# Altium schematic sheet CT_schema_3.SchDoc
size 322 x 229 mm
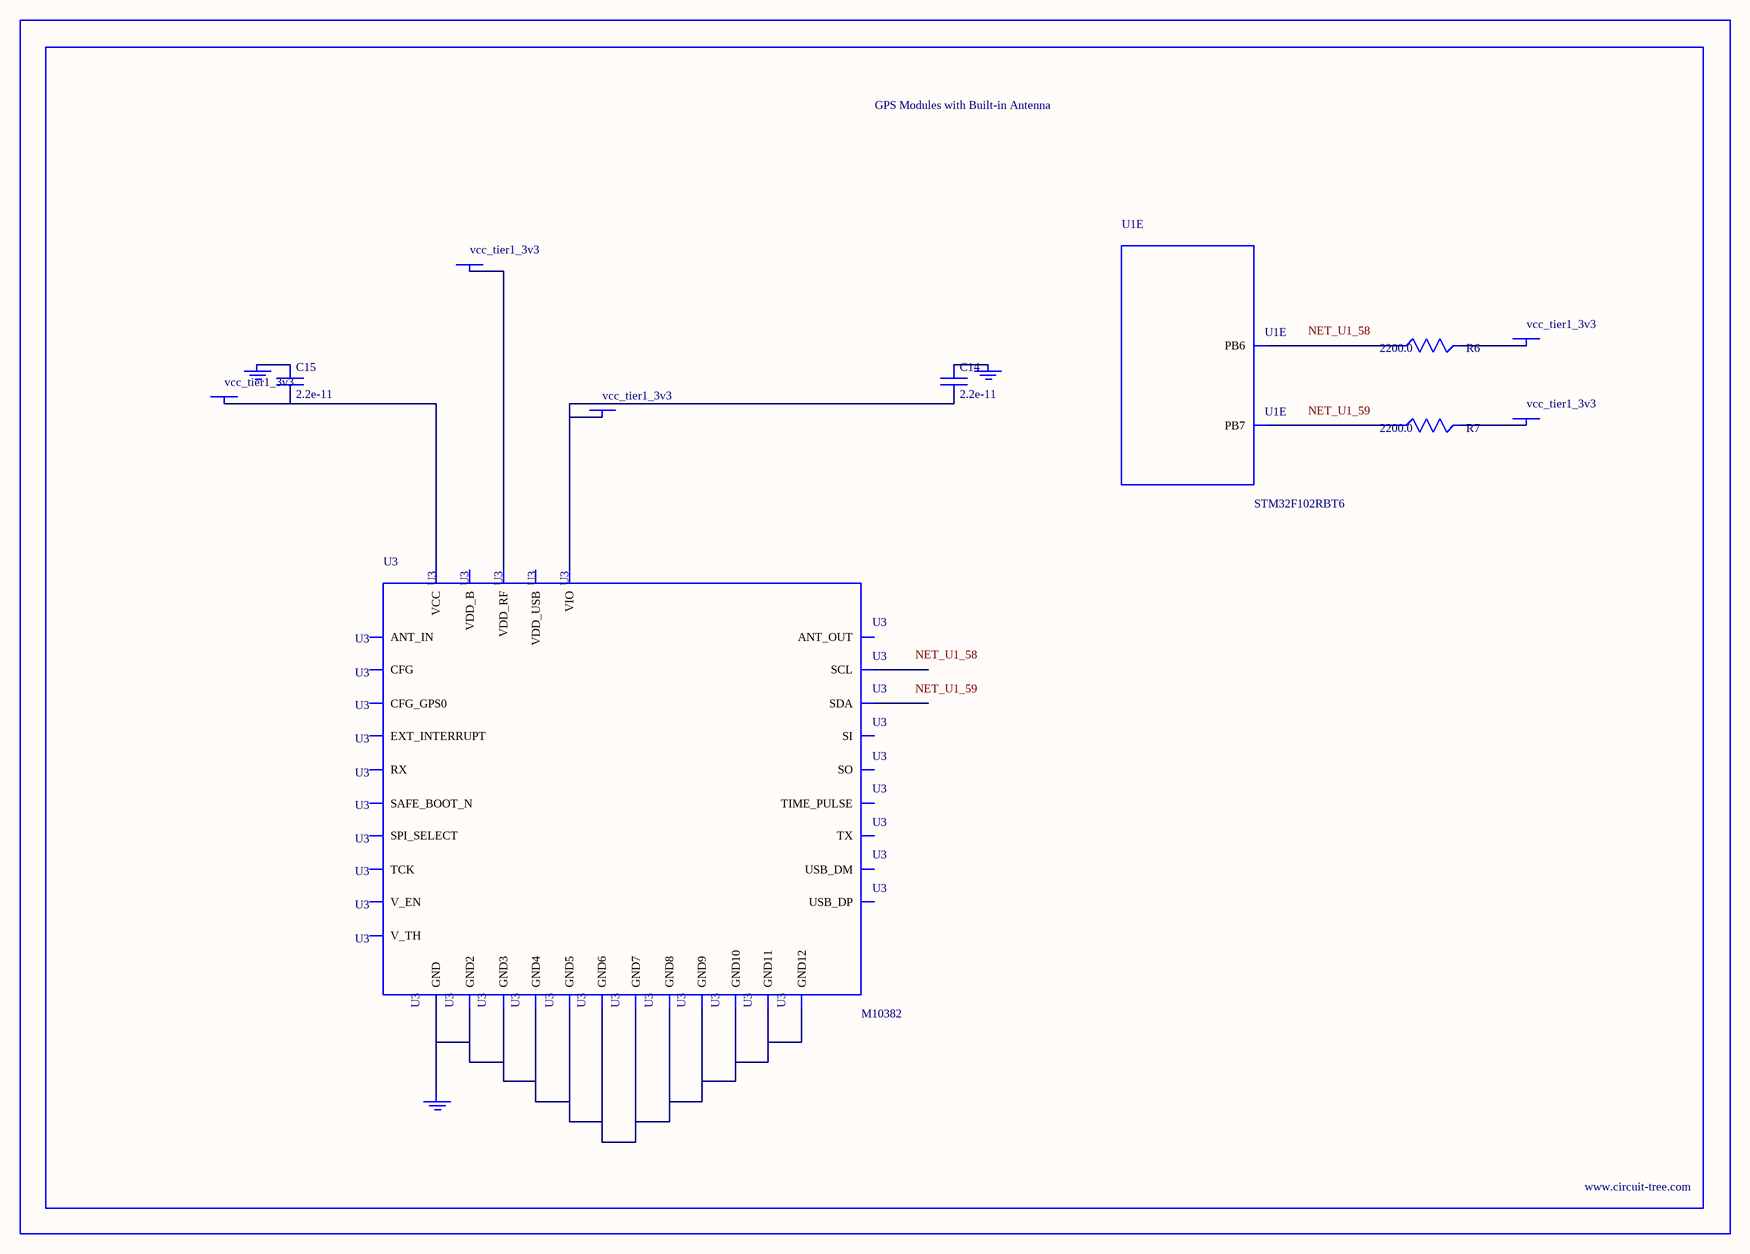
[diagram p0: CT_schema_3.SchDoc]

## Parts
BORDER2  (no value)
C14  2.2e-11  [C0402]
C15  2.2e-11  [C0402]
GND_INSTANCE_2_0  (no value)
GND_INSTANCE_2_1  (no value)
GND_INSTANCE_2_2  (no value)
POWER_INSTANCE_2_0  vcc_tier1_3v3
POWER_INSTANCE_2_1  vcc_tier1_3v3
POWER_INSTANCE_2_2  vcc_tier1_3v3
POWER_INSTANCE_2_3  vcc_tier1_3v3
POWER_INSTANCE_2_4  vcc_tier1_3v3
R6  2200.0  [R0603]
R7  2200.0  [R0603]
U1  STM32F102RBT6  [LQFP64]  (part E of 7)
U3  M10382  [M10382]

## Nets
NetC14_1: C14.1 GND_INSTANCE_2_0.0(GND)
NetC14_2: C14.2 POWER_INSTANCE_2_0.0(PWR) U3.5(VIO)
NetC15_1: C15.1 GND_INSTANCE_2_1.0(GND)
NetC15_2: C15.2 POWER_INSTANCE_2_2.0(PWR) U3.27(VCC)
NetGND_INSTANCE_2_2_0: GND_INSTANCE_2_2.0(GND) U3.2(GND) U3.4(GND2) U3.14(GND3) U3.17(GND4) U3.21(GND5) U3.24(GND6) U3.26(GND7) U3.28(GND8) U3.33(GND9) U3.34(GND10) U3.35(GND11) U3.36(GND12)
NetPOWER_INSTANCE_2_1_0: POWER_INSTANCE_2_1.0(PWR) U3.25(VDD_RF)
NetPOWER_INSTANCE_2_3_0: POWER_INSTANCE_2_3.0(PWR) R6.2
NetPOWER_INSTANCE_2_4_0: POWER_INSTANCE_2_4.0(PWR) R7.2
NetR6_1: R6.1 U1.58(PB6)
NetR7_1: R7.1 U1.59(PB7)

Not connected (* = marked no-connect by the designer): U3 1(ANT_IN) 3(ANT_OUT) 6(USB_DP) 7(USB_DM) 8(SO) 9(CFG_GPS0) 10(SPI_SELECT) 11(TX) 12(V_TH) 13(RX) 15(VDD_B) 16(SI) 18(SDA) 19(SCL) 20(SAFE_BOOT_N) 22(TCK) 23(TIME_PULSE) 29(EXT_INTERRUPT) 30(V_EN) 31(CFG) 32(VDD_USB)

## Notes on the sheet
- Labels drawn without touching a wire or pin: NET_U1_58, NET_U1_59

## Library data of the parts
BORDER2 = BORDER_PAGE2
C14 C15 = C0402C220K3RAC
GND_INSTANCE_2_0-GND_INSTANCE_2_2 = GND
POWER_INSTANCE_2_0-POWER_INSTANCE_2_4 = PWR
R6 R7 = RC0603JR-072K2L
